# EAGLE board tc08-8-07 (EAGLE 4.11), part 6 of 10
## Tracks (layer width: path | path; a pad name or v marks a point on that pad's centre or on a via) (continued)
IM_05\  (via drill 0.61) (continued)
  Bottom 0.254: B04.S1 326.11,161.59 327.06,160.64 334.05,160.64 335,161.59 337.54,161.59 B03.S1 | v285.79,37.45 287.69,37.45 292.77,42.53 307.06,42.53 307.38,42.21 308.65,42.21 309.28,42.85 313.09,42.85 313.73,42.21 316.58,42.21 317.54,43.17 320.71,43.17 321.66,44.12 D04.L1 | v282.61,15.54 281.98,14.91 265.47,14.91 265.15,14.59 260.39,14.59 v260.07,14.91 | v256.26,11.1 255.94,11.42 238.48,11.42 238.16,11.1 v235.94,11.1 | v234.67,21.58 234.03,20.94 218.48,20.94 213.4,15.86 181.65,15.86 181.01,16.5 178.79,16.5 178.15,15.86 110.53,15.86 109.26,17.13 v96.24,17.13 | v94.65,83.17 98.14,86.66 v99.1,86.66 | v106.72,210.17 v109.57,213.03 | v109.57,222.24 110.84,223.51 134.02,223.51 134.66,224.14 138.15,224.14 141.01,227 v151.48,227 | v158.15,269.55 159.74,271.13 166.09,271.13 166.41,271.45 187.36,271.45 v188,270.81 | v190.54,272.72 190.85,272.4 194.03,272.4 194.66,271.77 205.46,271.77 205.78,272.09 207.05,272.09 207.36,271.77 214.98,271.77 217.21,273.99 219.75,273.99 220.38,274.62 v221.02,274.62 | v241.02,287.96 241.34,288.28 266.74,288.28 268.96,286.05 303.25,286.05 303.88,286.69 320.71,286.69 v321.03,287.01 321.35,286.69 363.26,286.69 v365.16,284.79 | v349.92,176.52 v347.06,173.66 | v350.24,179.37 349.6,180.01 349.6,191.12 352.46,191.12 v353.73,192.39 | v356.91,195.57 356.91,198.43 355.64,199.7 v355.64,200.96 | v364.21,223.19 367.07,226.05 369.92,226.05 370.56,226.68 370.56,230.18 v368.97,230.18 | v368.97,241.29 368.97,249.54 v365.48,249.54
IM_06\  (via drill 0.61)
  Top 0.254: v368.34,43.17 369.61,44.44 369.61,72.69 370.88,73.97 370.88,94.92 370.24,95.55 370.24,97.46 371.83,99.05 371.83,114.29 371.51,114.61 371.51,147.94 373.42,149.85 373.42,239.06 v372.78,239.7 | v339.13,196.2 339.44,196.52 339.44,209.86 338.81,210.49 338.81,224.14 339.44,224.78 339.44,233.03 339.13,233.35 339.13,237.16 340.08,238.11 v340.08,239.7
  Bottom 0.254: 327.38,188.58 327.7,188.58 328.97,187.31 B03.H2 | 327.38,188.58 320.71,188.58 319.76,187.63 B04.H2 | v368.34,43.17 364.53,39.36 349.92,39.36 349.6,39.68 327.38,39.68 326.11,40.95 D04.M1 | v372.78,239.7 v340.08,239.7 336.59,243.19 327.06,243.19 326.11,244.14 A04.M1 | 327.38,188.58 327.38,192.08 337.54,192.08 337.86,192.39 338.81,192.39 339.44,193.03 339.44,196.2 v339.13,196.2
IM_07\
  Top 0.254: D04.P1 325.79,35.55 326.43,36.18 326.43,40.31 327.06,40.95 327.06,48.57 327.38,48.88 327.38,50.15 326.74,50.79 326.74,55.23 326.43,55.55 326.43,59.36 327.06,60 327.06,100.32 326.74,100.63 326.74,119.69 327.06,120 327.06,132.07 326.74,132.39 326.74,146.67 327.38,147.31 327.38,182.55 328.33,183.5 B03.J2 328.33,184.77 328.33,187.31 326.74,188.9 326.74,204.14 327.06,204.46 327.06,215.25 326.74,215.57 326.74,232.4 326.43,232.71 326.43,236.84 325.79,237.48 A04.P1
  Bottom 0.254: B04.J2 316.58,184.46 317.54,185.41 325.16,185.41 326.11,184.46 328.01,184.46 B03.J2
IM_08\  (via drill 0.61)
  Top 0.254: v368.65,33.64 370.24,35.23 370.24,72.38 371.51,73.65 371.51,95.24 370.88,95.87 370.88,97.14 372.46,98.73 v372.46,114.92 | v356.59,146.67 356.27,146.99 356.27,154.61 355.32,155.56 v355.32,163.18 355.32,169.21 355.95,169.85 355.95,177.47 359.13,180.64 359.13,194.93 358.81,195.25 358.81,197.15 359.45,197.79 359.45,200.65 358.81,201.28 358.81,203.51 360.08,204.77 360.08,206.05 361.99,207.95 361.99,218.11 361.67,218.43 361.67,226.36 361.99,226.68 361.99,228.9 361.67,229.22 v361.67,233.03 | v344.84,166.36 v344.84,163.5
  Bottom 0.254: v368.65,33.64 347.7,33.64 344.84,30.78 343.89,30.78 343.25,30.15 337.86,30.15 337.22,29.51 333.41,29.51 333.09,29.83 331.19,29.83 330.87,29.51 326.74,29.51 326.11,28.88 D04.S1 | v372.46,114.92 369.61,117.78 369.61,146.67 364.53,146.67 364.21,146.36 356.91,146.36 v356.59,146.67 | v355.32,163.18 345.16,163.18 v344.84,163.5 | v344.84,166.36 344.21,166.99 343.25,166.99 335.63,174.61 333.73,174.61 332.46,175.88 331.19,175.88 328.97,173.66 328.97,172.07 B03.N2 328.01,171.76 325.79,171.76 324.84,172.71 317.54,172.71 316.58,171.76 B04.N2 | v361.67,233.03 350.24,233.03 349.92,232.71 346.11,232.71 345.79,233.03 343.89,233.03 343.57,232.71 339.76,232.71 339.44,233.03 337.54,233.03 337.22,232.71 334.36,232.71 334.05,233.03 331.19,233.03 330.87,232.71 326.74,232.71 326.11,232.08 A04.S1
IM_09\  (via drill 0.61)
  Top 0.254: 314.68,167.95 314.68,151.75 315.31,151.12 315.31,140.96 314.68,140.32 314.68,88.25 315.95,86.98 315.95,73.33 314.68,72.06 314.68,69.2 315,68.88 315,64.76 315.63,64.12 D04.D2 | 314.68,167.95 v316.58,169.85 | 314.68,167.95 314.68,203.82 315.95,205.09 315.95,219.7 314.68,220.97 314.68,230.49 314.36,230.81 314.36,264.78 315.63,266.05 A04.D2
  Bottom 0.254: v316.58,169.85 316.9,169.53 330.24,169.53 331.19,168.58 B03.P2
IM_10\  (via drill 0.61)
  Top 0.254: v319.44,51.74 317.85,53.33 317.85,54.6 318.17,54.92 318.17,59.04 318.81,59.68 D04.E2 | v321.66,52.38 321.35,52.06 321.35,51.74 321.03,51.42 321.03,48.57 v321.35,48.25 | v314.04,45.71 313.73,45.39 313.73,42.21 314.36,41.58 314.36,39.36 313.73,38.72 313.73,35.86 314.36,35.23 314.36,33.96 v314.04,33.64 | v303.57,28.25 301.98,26.66 301.98,22.85 v302.3,22.53 | v288.01,20.31 287.69,19.99 287.69,9.19 283.25,4.75 276.9,4.75 276.9,18.09 276.58,18.4 276.58,20.94 v276.9,21.26 | v193.08,77.77 192.12,78.73 192.12,83.81 v192.44,84.13
  Route2 0.254: v270.55,21.89 255.62,36.82 254.35,36.82 252.77,35.23 252.13,35.23 v249.59,37.77 | v192.44,84.13 202.92,94.6 202.92,98.41 204.19,99.68 205.14,99.68 206.09,100.63 206.09,101.59 207.36,102.86 208,102.86 209.59,104.44 209.59,106.67 210.54,107.62 210.54,108.57 212.44,110.48 212.44,122.86 225.14,135.56 225.14,140.96 245.46,161.28 245.46,161.91 v244.51,162.86 | v252.77,160.96 253.72,161.91 253.72,162.86 261.66,170.8 261.66,172.39 263.24,173.98 263.24,177.79 v266.74,181.28 | v264.2,194.61 262.61,196.2 269.91,203.51 269.91,207.31 263.88,213.35 269.28,218.74 270.23,218.74 270.55,219.06 272.77,219.06 277.21,223.51 278.17,223.51 278.8,224.14 278.8,226.36 284.2,231.76 285.47,231.76 290.23,236.52 313.73,236.52 318.81,241.61 320.71,241.61 331.19,252.08 331.82,252.08 333.73,253.99 333.73,257.16 336.59,260.02 336.59,260.66 327.38,269.86 322.93,265.42 321.35,265.42 319.76,263.83 A04.E2
  Route15 0.254: v242.92,37.77 234.99,45.71 234.99,46.66 234.03,47.61 232.76,47.61 223.87,56.5 223.24,56.5 221.33,58.41 217.52,58.41 216.25,59.68 216.25,60.63 215.3,61.58 214.35,61.58 v199.11,76.82 | v244.51,162.86 245.46,162.86 246.42,163.82 248,163.82 248.96,164.77 v252.77,160.96 | v266.74,181.28 268.64,183.18 267.69,184.14 267.69,186.04 267.05,186.68 267.05,187.95 v268.01,188.9
  Bottom 0.254: v319.44,51.74 319.76,52.06 321.35,52.06 v321.66,52.38 | v321.35,48.25 321.35,46.34 314.68,46.34 v314.04,45.71 | v314.04,33.64 313.73,33.32 308.65,33.32 v303.57,28.25 | v302.3,22.53 300.07,20.31 v288.01,20.31 | v276.9,21.26 276.58,20.94 271.82,20.94 270.86,21.89 v270.55,21.89 | v249.59,37.77 249.27,37.45 247.37,37.45 246.73,36.82 243.88,36.82 v242.92,37.77 | v199.11,76.82 198.16,77.77 v193.08,77.77 | v268.01,188.9 268.64,189.54 269.59,189.54 270.23,190.17 270.23,192.39 267.05,192.39 264.83,194.61 v264.2,194.61
IM_11\  (via drill 0.61)
  Top 0.254: v319.12,58.09 318.81,57.77 318.81,54.6 D04.H2 | v352.46,83.49 352.78,83.81 352.78,90.79 v353.1,91.11 | v360.72,130.16 361.67,131.11 361.67,133.97 360.4,135.24 v360.4,137.46 | v321.35,256.53 321.03,256.21 321.03,251.77 v321.35,251.45 | v318.81,249.23 317.54,247.96 317.54,233.35 315.63,231.45 v315.63,230.81 | v312.46,229.54 311.82,228.9 311.82,226.36 311.5,226.05 311.5,222.87 312.77,221.6 v312.77,219.38 | v318.17,211.12 321.35,207.95 321.35,204.14 v320.71,203.51 | v325.79,190.8 326.11,190.49 326.11,188.58 327.38,187.31 v327.38,185.73 | v335,180.01 333.73,178.74 333.73,167.63 v334.68,166.68
  Route2 0.254: v360.72,124.13 357.86,126.99 360.72,129.84 v360.72,130.16 | v315.63,230.81 314.04,229.22 312.77,229.22 v312.46,229.54
  Route15 0.254: v323.25,60.31 338.49,75.55 338.17,75.87 338.17,76.82 342.62,81.27 342.94,80.95 344.52,80.95 v346.11,79.36 | v357.54,108.25 360.4,111.11 v357.22,114.29 | v356.59,140.01 356.59,141.59 355.64,142.55 355.64,147.94 348.65,154.93 348.65,155.88 345.48,159.05 342.94,159.05 341.98,160.01 336.59,160.01 332.14,164.45 | 332.14,164.45 v329.28,167.31 | v320.71,203.51 320.71,202.87 321.98,201.6 321.98,200.33 324.2,198.11 324.2,196.84 326.74,194.3 326.74,191.76 v325.79,190.8 | v331.82,185.73 330.55,184.46 v335,180.01 | v334.68,166.68 332.46,164.45 332.14,164.45
  Bottom 0.254: v319.12,58.09 320.08,59.04 320.08,59.36 321.03,60.31 v323.25,60.31 | v346.11,79.36 349.29,82.54 351.51,82.54 v352.46,83.49 | v353.1,91.11 354.68,92.7 355.95,92.7 356.91,93.65 360.72,93.65 366.11,99.05 367.07,99.05 368.65,100.63 368.65,107.3 361.67,107.3 361.03,106.67 359.13,106.67 v357.54,108.25 | v357.22,114.29 357.22,115.24 355.95,116.51 355.95,119.37 361.35,119.37 363.26,121.27 366.75,121.27 367.07,120.96 367.7,120.96 368.34,121.59 368.34,122.86 364.53,122.86 364.21,122.54 362.3,122.54 v360.72,124.13 | v360.4,137.46 357.86,140.01 v356.59,140.01 | v329.28,167.31 328.97,166.99 324.52,166.99 322.93,168.58 319.76,168.58 B04.P2 | v321.35,256.53 320.08,256.53 319.76,256.85 A04.H2 | v321.35,251.45 321.35,249.23 v318.81,249.23 | v312.77,219.38 317.54,214.62 317.54,211.12 v318.17,211.12 | v327.38,185.73 328.33,186.68 330.55,186.68 331.51,185.73 v331.82,185.73
INT_RQ\  (via drill 0.61)
  Top 0.254: v282.93,233.35 282.29,232.71 282.29,223.83 281.66,223.19 281.66,216.84 v282.61,215.89
  Route15 0.254: v246.42,236.52 242.92,240.02 239.11,240.02 230.22,248.91 229.27,248.91 228.95,249.23 227.37,249.23 226.1,250.49 224.51,250.49 A12.K1 | v299.12,214.93 299.12,212.08 304.84,206.36 304.84,206.05 306.11,204.77 307.69,204.77 308.96,203.51 B05.B1
  Bottom 0.254: v246.42,236.52 246.73,236.21 268.01,236.21 270.55,233.67 280.71,233.67 281.34,234.3 281.98,234.3 v282.93,233.35 | v282.61,215.89 283.25,215.25 298.8,215.25 v299.12,214.93
IOP_1  (via drill 0.61)
  Top 0.254: v356.27,49.52 355.95,49.83 355.95,69.2 v356.27,69.52 | v335.63,71.43 335.63,87.62 336.27,88.25 336.27,91.43 v334.36,93.33 | v311.5,93.97 311.82,94.28 311.82,97.46 311.5,97.78 311.5,100 312.14,100.63 312.14,103.18 v311.19,104.13 | v344.52,248.59 A02.K2
  Route2 0.254: v363.89,233.99 371.19,226.68 371.19,225.73 368.65,223.19 368.65,220.97 368.34,220.65 368.34,214.62 372.78,210.17 372.78,150.17 371.19,148.58 371.19,147.62 370.88,147.31 370.88,106.35 372.78,104.44 372.78,98.1 371.51,96.83 371.51,72.38 370.88,71.74 370.88,71.11 v371.83,70.16
  Route15 0.254: v344.52,248.59 344.84,248.59 354.37,239.06 v354.37,238.75 | v371.83,60.95 371.83,56.18 371.19,55.55 v372.46,54.28
  Bottom 0.254: 311.19,104.44 307.06,104.44 C05.P2 | 311.19,104.44 312.14,103.49 317.54,103.49 318.49,104.44 C04.P2 | v356.27,69.52 354.37,71.43 v335.63,71.43 | v334.36,93.33 330.24,93.33 329.6,92.7 326.74,92.7 325.79,93.65 317.85,93.65 316.9,92.7 315,92.7 313.73,93.97 v311.5,93.97 | v311.19,104.13 311.19,104.44 | D02.K2 345.16,47.93 345.79,48.57 349.92,48.57 350.87,49.52 v356.27,49.52 367.7,49.52 v372.46,54.28 | v354.37,238.75 356.27,236.84 357.86,236.84 359.45,238.43 360.72,238.43 363.89,235.26 v363.89,233.99 | v371.83,70.16 v371.83,60.95
IOP_2  (via drill 0.61)
  Top 0.254: v358.81,40.95 358.49,41.26 v358.49,67.93 | v329.28,71.74 328.97,72.06 v328.97,87.3 | v308.01,88.57 308.33,88.89 308.33,89.52 308.96,90.16 308.96,92.7 v308.33,93.33 | v303.57,98.1 303.57,100.95 C05.R2 | v331.82,247.32 331.51,247 331.51,246.68 330.55,245.73 330.55,243.19 v331.51,242.24 | v287.69,171.76 286.1,170.17 v286.1,150.8
  Route2 0.254: v331.51,242.24 316.58,227.32 316.27,227.32 315.63,226.68 315.63,223.83 314.68,222.87 314.68,220.33 314.04,219.7 314.04,210.17 306.11,202.24 305.15,202.24 v286.74,183.82
  Route15 0.254: v303.57,98.1 v308.33,93.33 | v286.74,183.82 286.74,183.5 288.64,181.6 288.64,172.71 v287.69,171.76 | v286.1,150.8 286.1,141.59 288.64,139.05 288.64,138.1 289.28,137.46 289.28,132.39 299.12,122.54 299.12,121.27 299.44,120.96 299.44,120 301.34,118.1 301.34,111.75 304.52,108.57 304.52,103.18 303.57,102.22 C05.R2
  Bottom 0.254: C05.R2 303.88,101.91 308.01,101.91 308.96,102.86 310.23,102.86 311.19,101.91 315.31,101.91 C04.R2 | v358.81,40.95 357.86,39.99 350.24,39.99 349.92,40.31 345.79,40.31 345.16,40.95 D02.M2 | v358.49,67.93 357.86,68.57 334.05,68.57 330.87,71.74 v329.28,71.74 | v328.97,87.3 328.65,86.98 309.6,86.98 v308.01,88.57 | v331.82,247.32 332.14,247.32 333.09,246.37 338.17,246.37 339.13,245.42 343.25,245.42 343.89,244.78 A02.M2
IOP_4  (via drill 0.61)
  Top 0.254: 342.62,96.83 342.62,92.06 344.52,90.16 344.52,74.92 342.94,73.33 342.94,40.95 343.57,40.31 343.57,36.18 344.21,35.55 D02.P2 | 342.62,96.83 v341.03,98.41 | 342.62,96.83 342.62,133.97 342.3,134.29 342.3,137.15 342.62,137.46 342.62,140.32 342.3,140.64 342.3,143.5 342.94,144.13 342.94,180.64 342.62,180.96 342.62,197.47 342.3,197.79 342.3,200.65 342.62,200.96 342.62,206.36 344.52,208.27 344.52,222.24 342.94,223.83 342.94,232.08 343.57,232.71 343.57,236.84 344.21,237.48 A02.P2
  Bottom 0.254: 317.54,99.68 312.14,99.68 311.19,98.73 307.06,98.73 C05.S2 | 317.54,99.68 318.49,98.73 C04.S2 | v341.03,98.41 339.76,99.68 317.54,99.68
LDMF  (via drill 0.61)
  Top 0.254: v228.64,55.55 228.32,55.87 228.32,59.36 227.05,60.63 D11.D2 227.37,64.12 227.37,67.93 v227.68,68.25 | v291.18,110.48 290.23,111.43 v290.23,112.38 | v256.26,96.51 255.62,95.87 v255.62,93.97 | v243.24,89.52 242.92,89.21 v242.92,79.36
  Route2 0.254: v294.04,113.33 306.74,126.03 306.74,126.99 309.6,129.84 312.14,129.84 C05.E1 | v284.52,112.7 279.75,112.7 274.36,107.3 273.72,107.3 v268.64,102.22 | v243.24,89.52 v245.78,92.06 | v236.26,78.09 236.26,74.6 235.3,73.65 235.3,72.06 233.72,70.47 D11.B1
  Bottom 0.254: v228.64,55.55 230.54,55.55 231.49,54.6 235.62,54.6 235.94,54.28 D11.H1 | v227.68,68.25 231.49,68.25 232.76,69.52 D11.B1 | v291.18,110.48 v294.04,113.33 | v290.23,112.38 289.91,112.7 v284.52,112.7 | v268.64,102.22 267.69,101.27 266.74,101.27 265.78,100.32 265.15,100.32 263.24,98.41 263.24,97.14 260.7,97.14 260.07,97.78 257.53,97.78 v256.26,96.51 | v255.62,93.97 254.35,92.7 250.54,92.7 249.91,93.33 247.05,93.33 v245.78,92.06 | v242.92,79.36 241.65,78.09 v236.26,78.09
LDMF\  (via drill 0.61)
  Top 0.254: v309.28,137.15 309.28,136.51 308.33,135.56 308.33,128.58 309.28,127.62 C05.F1 | v318.49,139.05 319.44,140.01 v319.44,140.96 | v321.98,143.18 321.98,148.58 v319.44,151.12 | v285.15,161.59 285.47,161.91 285.47,165.72 v284.52,166.68
  Route15 0.254: v294.04,152.71 v285.15,161.59
  Bottom 0.254: v309.28,137.15 309.92,137.78 317.22,137.78 v318.49,139.05 | v319.44,140.96 321.66,143.18 v321.98,143.18 | v319.44,151.12 319.12,150.8 309.28,150.8 308.65,151.43 304.2,151.43 303.88,151.12 295.63,151.12 v294.04,152.71 | v284.52,166.68 284.2,166.99 269.91,166.99 268.96,167.95 B08.P2
LPB_00  (via drill 0.61)
  Top 0.254: v46.71,218.11 46.71,221.6 48.3,223.19 48.3,227.32 48.93,227.95 A25.T2 | v44.8,216.21 44.17,215.57 44.17,47.29 50.52,40.95 50.52,39.04 v80.36,9.19 | v269.59,7.93 269.59,44.44 266.74,47.29 v266.74,56.5 | v269.91,126.35 269.91,127.3 270.86,128.26 270.86,132.39 271.18,132.7 C08.D1 | v290.87,92.38 291.82,91.43 291.82,83.17 291.18,82.54 291.18,74.28 v291.5,73.97 | v278.8,67.93 277.85,66.98 v277.85,65.39
  Route15 0.254: v274.67,121.59 v269.91,126.35 | v268.64,115.24 284.83,99.05 284.83,98.41 v290.87,92.38
  Bottom 0.254: v44.8,216.21 v46.71,218.11 | v80.36,9.19 81.95,7.61 222.29,7.61 222.92,8.24 230.86,8.24 232.76,6.34 259.12,6.34 260.39,7.61 269.28,7.61 v269.59,7.93 | v266.74,56.5 270.23,60 272.45,60 | 272.45,60 274.04,60 D08.E1 | v274.67,121.59 275.94,121.59 276.58,120.96 276.58,118.73 272.13,118.73 v268.64,115.24 | v291.5,73.97 288.64,71.11 282.61,71.11 279.44,67.93 v278.8,67.93 | 272.45,60 v277.85,65.39
LPB_00\  (via drill 0.61)
  Top 0.254: v260.07,39.99 260.7,40.63 260.7,51.1 v261.66,52.06
  Bottom 0.254: v260.07,39.99 250.86,39.99 249.91,40.95 D10.M1 | v261.66,52.06 262.29,52.69 264.2,52.69 268.32,56.82 270.86,56.82 D08.F1
LPB_01  (via drill 0.61)
  Top 0.254: v13.05,78.09 19.09,72.06 v19.09,44.75 | v275.31,7.61 275.94,8.24 275.94,36.5 271.82,40.63 271.82,43.8 D08.L1 | v296.26,92.38 298.17,90.47 298.17,85.08 297.22,84.13 v297.22,71.43 | v291.18,65.39 v291.18,67.93
  Route15 0.254: v271.5,110.8 268.32,107.62 271.82,104.13 v271.82,103.81 | v287.37,101.59 287.37,101.27 v296.26,92.38
  Bottom 0.254: v13.05,78.09 5.43,78.09 5.43,219.7 12.42,226.68 37.5,226.68 37.82,227 40.04,227 40.36,226.68 42.26,226.68 44.8,224.14 46.71,224.14 47.03,224.46 51.15,224.46 51.79,225.09 A25.U2 | v19.09,44.75 56.87,6.97 222.6,6.97 223.24,7.61 230.54,7.61 232.45,5.7 259.43,5.7 260.7,6.97 274.67,6.97 v275.31,7.61 | v271.5,110.8 272.45,110.8 273.72,112.07 273.72,112.7 273.09,113.33 272.45,113.33 272.13,113.02 270.23,113.02 270.23,115.88 271.18,116.83 273.72,116.83 274.04,117.14 C08.K1 | v271.82,103.81 272.13,103.49 275.94,103.49 276.58,104.13 279.75,104.13 281.02,102.86 286.1,102.86 v287.37,101.59 | v297.22,71.43 296.9,71.11 294.68,71.11 291.5,67.93 v291.18,67.93 | v291.18,65.39 291.18,64.76 291.82,64.12 291.82,60 290.55,60 288.33,57.77 288.33,54.92 288.64,54.6 288.64,48.88 285.47,48.88 282.93,46.34 274.04,46.34 272.45,44.75 272.13,44.75 D08.L1
LPB_01\  (via drill 0.61)
  Top 0.254: v261.97,38.72 262.29,38.4 v262.29,36.82
  Bottom 0.254: v261.97,38.72 260.07,38.72 259.43,39.36 247.69,39.36 246.73,38.4 D10.N1 | v262.29,36.82 268.32,36.82 272.45,40.95 274.04,40.95 D08.M1
LPB_02  (via drill 0.61)
  Top 0.254: v55.92,218.11 55.92,219.06 52.74,219.06 49.88,221.92 A25.V2 | v45.12,209.22 44.8,208.9 44.8,90.16 47.03,87.94 47.03,73.97 51.15,69.84 51.15,40.63 v77.19,14.59 | v273.4,9.51 v273.4,26.02 | v294.04,90.16 294.36,89.84 294.36,74.28 294.99,73.65 294.99,71.11 294.36,70.47 v294.36,69.52 | v296.26,65.08 v296.26,67.61 | v273.72,37.14 273.4,36.82 273.4,30.15 274.36,29.2 D08.S1
  Route15 0.254: v273.72,101.59 273.72,101.27 v283.88,91.11
  Bottom 0.254: v55.92,218.11 55.92,217.48 57.19,216.21 57.19,210.17 54.65,210.17 53.38,208.9 45.44,208.9 v45.12,209.22 | v77.19,14.59 82.9,8.88 221.65,8.88 222.29,9.51 231.49,9.51 233.4,7.61 258.48,7.61 260.39,9.51 v273.4,9.51 | v273.4,26.02 273.4,28.25 274.04,28.25 D08.S1 | v283.88,91.11 284.83,90.16 v294.04,90.16 | v296.26,67.61 v294.36,69.52 | v296.26,65.08 292.45,61.27 292.45,59.36 290.87,59.36 288.96,57.46 288.96,55.23 292.14,52.06 292.14,50.15 291.82,50.15 284.83,43.17 279.75,43.17 v273.72,37.14 | v273.72,101.59 C08.R1
LPB_02\  (via drill 0.61)
  Top 0.254: v271.18,33.64 272.77,33.64 272.77,27.93 274.36,26.34 274.36,22.85 D08.U1
  Bottom 0.254: v271.18,33.64 250.86,33.64 249.91,34.6 D10.P1
LPB_03  (via drill 0.61)
  Top 0.254: D08.H2 268.01,54.6 267.69,54.92 267.69,58.09 266.42,59.36 266.42,64.76 266.1,65.08 266.1,68.88 266.74,69.52 266.74,118.1 268.32,119.69 C08.H2 | v30.52,274.62 28.29,274.62 28.29,247.64 25.75,245.1 25.75,243.83 27.34,242.24 v27.34,240.65 | v40.68,223.83 40.04,223.19 v40.04,219.7 | v47.98,211.44 48.61,210.81 48.61,207 51.47,204.14 51.47,200.96 51.15,200.65 51.15,148.26 54.33,145.08 54.33,107.3 v55.92,105.72 | v115.61,95.24 116.56,94.28 116.56,93.33 120.69,89.21 120.69,86.98 v122.59,85.08 | v151.17,74.92 158.47,74.92 158.47,57.77 161.64,54.6 161.64,29.83 v162.6,28.88 | v175.3,27.61 178.47,27.61 v180.06,26.02
  Route2 0.254: v146.4,79.68 v151.17,74.92 | v213.4,28.56 217.21,24.75 220.06,27.61 221.02,27.61 223.24,29.83 229.59,29.83 239.11,39.36 244.19,39.36 245.46,40.63 246.73,40.63 251.81,45.71 254.67,45.71 255.31,46.34 256.58,46.34 258.8,48.57 261.02,48.57 264.51,52.06 266.1,52.06 267.69,53.64 D08.H2
  Route15 0.254: v27.34,240.65 34.33,233.67 34.33,232.71 41.31,225.73 41.31,224.46 v40.68,223.83 | v180.06,26.02 182.28,23.8 185.46,23.8 191.49,29.83 194.03,29.83 v194.35,29.51
  Bottom 0.254: v30.52,274.62 37.82,274.62 39.09,275.9 A26.A2 | v40.04,219.7 46.71,213.03 47.03,213.03 47.98,212.08 v47.98,211.44 | v55.92,105.72 64.49,97.14 113.7,97.14 v115.61,95.24 | v122.59,85.08 127.99,79.68 v146.4,79.68 | v162.6,28.88 163.55,27.93 165.45,27.93 166.09,27.29 167.36,27.29 167.68,27.61 172.12,27.61 172.44,27.29 174.98,27.29 v175.3,27.61 | v194.35,29.51 194.66,29.83 211.81,29.83 213.08,28.56 v213.4,28.56
LPB_03\  (via drill 0.61)
  Top 0.254: v267.37,32.06 267.05,32.37 267.05,46.03 265.47,47.61 265.47,50.15 D08.J2
  Bottom 0.254: v267.37,32.06 265.78,30.47 251.81,30.47 251.18,31.1 247.05,31.1 246.73,31.42 D10.R1
LPB_04  (via drill 0.61)
  Top 0.254: v303.57,65.39 304.2,66.03 304.2,68.88 304.52,69.2 304.52,71.43 303.57,72.38 v303.57,76.5 | v268.32,85.08 270.23,86.98 270.23,89.52 271.5,90.79 271.5,92.7 v272.45,93.65 | v13.05,271.13 12.42,270.5 12.42,247 9.88,244.46 9.88,55.23 v10.83,54.28 | v264.2,8.56 263.88,8.88 263.88,33.01 v265.47,34.6
  Route15 0.254: v272.45,93.65 274.04,95.24 266.74,102.54 266.74,106.03 265.47,107.3 C08.N2
  Bottom 0.254: v303.57,65.39 303.25,65.08 298.8,65.08 298.8,55.87 285.47,42.53 280.39,42.53 273.4,35.55 269.28,35.55 268.96,35.23 D08.P2 267.69,34.6 v265.47,34.6 | v303.57,76.5 303.25,76.19 282.93,76.19 281.98,77.14 281.02,77.14 279.75,75.87 269.91,75.87 266.74,79.05 266.74,85.08 v268.32,85.08 | v13.05,271.13 34.33,271.13 35.91,272.72 A26.B2 | v10.83,54.28 54.96,10.15 80.68,10.15 82.59,8.24 221.97,8.24 222.6,8.88 231.18,8.88 233.08,6.97 258.8,6.97 260.39,8.56 v264.2,8.56
LPB_04\
  Bottom 0.254: D10.R2 240.38,32.06 241.34,33.01 263.56,33.01 264.51,32.06 D08.R2
LPB_05  (via drill 0.61)
  Top 0.254: v270.55,20.62 270.23,20.31 270.23,8.56 274.36,4.43 274.36,1.57 274.67,1.26 309.28,1.26 309.28,13.96 v312.77,17.45 | v291.5,23.8 291.82,24.12 291.82,31.1 292.14,31.42 v292.14,33.96 | v281.66,38.72 279.75,40.63 279.75,51.1 280.39,51.74 280.39,52.38 v279.44,53.33 | v272.13,54.6 273.4,54.6 274.04,55.23 274.04,59.04 273.4,59.68 273.4,63.49 v273.72,63.81 | v267.69,68.57 v267.69,71.11 | v265.15,71.74 264.83,72.06 v264.83,85.08 | v267.69,88.25 268.01,88.57 268.01,91.43 C08.U2 | v26.71,202.24 v26.71,204.77 | v46.07,183.18 47.34,181.92 v47.34,144.45 | v61,130.8 60.68,130.48 60.68,43.8 v89.89,14.59 | v102.59,11.42 105.13,8.88 149.26,8.88 v149.26,18.72 | v154.02,19.04 156.56,16.5 179.74,16.5 v179.74,19.35 | v184.19,18.09 187.68,18.09 187.68,20.31 v189.27,21.89 | v241.34,18.09 v246.42,13.01 | v39.72,266.37 A26.C2
  Route2 0.254: v264.83,85.08 264.83,85.39 v267.69,88.25 | v149.26,18.72 151.48,16.5 v154.02,19.04 | v179.74,19.35 182.6,16.5 v184.19,18.09 | v205.14,18.72 207.36,16.5 209.27,18.4 209.9,18.4 213.71,22.21 215.62,22.21 216.89,23.48 218.16,23.48 225.14,16.5 234.03,16.5 v235.62,18.09
  Route15 0.254: v273.72,63.81 273.72,64.44 v271.82,66.35 | v10.83,214.93 v1.94,223.83 | v193.08,18.09 v189.27,21.89 | v246.42,13.01 248,13.01 252.77,17.77 254.04,17.77 254.67,17.13 262.93,17.13 264.51,18.72 D08.V2
  Bottom 0.254: v270.55,20.62 268.96,20.62 267.69,19.35 265.78,19.35 D08.V2 | v312.77,17.45 312.77,20.62 305.47,20.62 302.3,23.8 v291.5,23.8 | v292.14,33.96 289.6,36.5 283.88,36.5 v281.66,38.72 | v279.44,53.33 278.8,52.69 274.04,52.69 v272.13,54.6 | v271.82,66.35 269.59,68.57 v267.69,68.57 | v267.69,71.11 267.05,71.74 v265.15,71.74 | v39.72,266.37 38.14,264.78 7.97,264.78 1.62,258.43 1.62,232.71 2.26,232.71 2.89,232.08 2.89,223.83 v1.94,223.83 | v10.83,214.93 10.83,207.63 16.55,207.63 19.09,205.09 21.31,205.09 23.53,207.31 24.17,207.31 v26.71,204.77 | v26.71,202.24 35.28,193.66 35.28,180.64 37.82,180.64 38.45,181.28 38.45,182.87 45.76,182.87 v46.07,183.18 | v61,130.8 v47.34,144.45 | v89.89,14.59 93.06,11.42 v102.59,11.42 | v193.08,18.09 193.39,17.77 204.19,17.77 v205.14,18.72 | v235.62,18.09 235.94,17.77 241.02,17.77 v241.34,18.09
LPB_05\
  Top 0.254: D10.U2 242.29,22.53 240.07,24.75 D10.T2 240.38,25.71 242.61,27.93 D10.S2
  Bottom 0.254: D08.V1 268.32,19.04 266.42,17.13 250.86,17.13 246.1,21.89 243.56,21.89 D10.U2
LPB_NOT_EQ_1  (via drill 0.61)
  Top 0.254: v34.33,51.1 34.64,51.42 34.64,143.5 33.69,144.45 v33.69,151.43 | v89.57,171.76 89.25,172.07 89.25,182.23 v90.84,183.82 | v118.78,188.58 119.42,189.22 119.73,189.22 120.37,189.85 120.37,195.89 v122.59,198.11 | v125.13,200.33 127.35,202.55 127.35,212.08 128.94,213.67 v128.94,217.48 | v150.21,218.11 149.9,218.43 149.9,221.29 149.58,221.6 149.58,231.13 v150.85,232.4 | v159.74,233.35 161.01,234.62 161.01,236.52 161.64,237.16 v163.87,237.16
  Route2 0.254: v206.09,223.83 208.95,223.83 209.27,224.14 212.13,224.14 222.29,234.3 223.24,234.3 v236.57,247.64
  Route15 0.254: v196.25,28.56 204.51,20.31 208.63,20.31 210.22,18.72 211.81,18.72 214.03,16.5 215.62,18.09 217.84,18.09 221.02,14.91 223.87,14.91 226.1,12.69 232.13,12.69 238.16,18.72 239.11,18.72 D10.V2 | v170.22,237.16 171.8,237.16 v182.28,226.68 | v241.34,247 244.83,247 245.46,246.37 247.05,246.37 248.64,244.78 A10.M1
  Bottom 0.254: v196.25,28.56 194.03,28.56 192.76,29.83 93.06,29.83 92.75,29.51 91.48,29.51 90.52,30.47 54.96,30.47 v34.33,51.1 | v33.69,151.43 45.44,163.18 61.95,163.18 64.49,160.64 78.46,160.64 v89.57,171.76 | v90.84,183.82 93.06,186.04 111.8,186.04 114.34,188.58 v118.78,188.58 | v122.59,198.11 124.81,200.33 v125.13,200.33 | v128.94,217.48 129.26,217.16 147.04,217.16 147.99,218.11 v150.21,218.11 | v150.85,232.4 151.48,233.03 159.42,233.03 v159.74,233.35 | v163.87,237.16 165.77,237.16 166.09,236.84 169.9,236.84 v170.22,237.16 | v182.28,226.68 184.82,224.14 205.78,224.14 v206.09,223.83 | v236.57,247.64 236.89,247.32 238.16,247.32 239.11,246.37 240.7,246.37 v241.34,247
LPB_TO_DTB  (via drill 0.61)
  Top 0.254: C08.M2 268.64,111.75 269.59,112.7 269.59,116.83 271.18,118.41 271.18,120 C08.J1 | v265.47,122.22 265.47,126.35 C08.F2 | 275.94,120.64 275.94,106.35 274.99,105.4 C08.P1 | 275.94,120.64 275.94,134.93 274.99,135.88 C08.C1 274.99,137.15 275.94,138.1 v275.94,209.54 | v228,209.54 227.68,209.86 227.68,216.21 228.32,216.84 228.32,222.87 227.37,223.83 227.37,227.95 A11.T2 | 275.94,120.64 v275.63,120.64
  Bottom 0.254: v265.47,122.22 266.74,120.96 270.86,120.96 C08.J1 v275.63,120.64 | C08.T2 265.47,95.87 265.47,99.68 266.42,99.68 267.37,100.63 268.32,100.63 270.86,103.18 270.86,104.76 C08.P1 | v228,209.54 228.32,209.22 275.63,209.22 v275.94,209.54
M-STOP\  (via drill 0.61)
  Top 0.254: D14.L1 194.98,45.07 194.03,46.03 194.03,72.06 194.66,72.69 194.66,87.62 194.03,88.25 194.03,93.65 193.08,94.6 193.08,97.46 193.71,98.1 193.71,132.07 193.39,132.39 193.39,135.88 193.71,136.2 193.71,170.17 193.39,170.49 193.39,188.58 194.03,189.22 194.03,191.44 194.98,192.39 194.98,196.2 B14.D1 | v271.5,115.88 270.23,115.88 270.23,111.75 269.59,111.11 269.59,96.19 268.01,94.6 v268.01,93.97 | v264.51,92.38 263.88,91.74 263.88,76.82 264.2,76.5 264.2,70.79 263.88,70.47 263.88,65.71 v264.51,65.08 | v232.76,232.08 232.13,232.71 232.13,248.27 v233.08,249.23 | v212.44,248.91 212.44,221.92 210.22,219.7 210.22,207.31 209.9,207 209.9,202.55 v210.22,202.24 | v201.33,198.74 v204.51,201.92
  Bottom 0.254: v271.5,115.88 279.12,115.88 280.39,117.14 C07.K2 | v268.01,93.97 266.42,92.38 v264.51,92.38 | v264.51,65.08 262.29,62.85 260.07,62.85 256.26,59.04 247.05,59.04 246.42,58.41 244.19,58.41 237.84,52.06 212.76,52.06 206.41,45.71 196.89,45.71 195.93,44.75 D14.L1 | v232.76,232.08 235.94,232.08 A11.S1 | v233.08,249.23 232.76,248.91 226.1,248.91 224.19,247 221.97,247 221.33,246.37 219.43,246.37 216.89,248.91 v212.44,248.91 | v210.22,202.24 209.9,201.92 v204.51,201.92 | v201.33,198.74 199.74,197.15 195.93,197.15 B14.D1
MB_TO_DTB\
  Top 0.254: D12.F1 D12.J1 | D12.S1 223.56,29.2 223.24,29.51 223.24,33.64 222.6,34.28 222.6,42.53 223.56,43.49 223.56,46.98 D12.K1 223.56,48.25 223.56,53.33 D12.H1
  Bottom 0.254: D12.H1 223.24,54.28 221.02,56.5 D12.F1
MC00  (via drill 0.61)
  Top 0.254: v47.34,240.02 47.34,233.35 46.39,232.4 A26.S1 | v107.99,240.33 108.3,240.02 108.3,237.48 v109.89,235.89 | v171.17,230.49 171.8,229.86 171.8,222.87 v172.76,221.92 | v184.19,218.11 185.14,217.16 185.14,213.67 v186.09,212.71 | v221.02,59.36 219.43,57.77 219.43,55.87 v219.75,55.55 | v208.32,53.64 207.05,52.38 207.05,51.74 206.73,51.42 206.73,49.52 v207.05,49.2 | v202.28,47.93 200.38,46.03 200.38,43.49 201.97,41.9 v201.97,40.63 | v190.54,40.31 190.22,39.99 190.22,37.14 188.31,35.23 188.31,33.01 184.19,28.88 v184.19,28.56 | v163.87,26.98 161.96,26.98 v161.96,22.85 | v76.55,26.66 60.04,43.17 v60.04,183.18 | v61.95,188.27 63.22,189.54 63.22,196.84 64.49,198.11 64.49,198.74 63.85,199.38 63.85,210.81 v64.17,211.12 | v64.17,217.48 v64.17,221.29
  Route2 0.254: v230.54,62.22 234.03,62.22 234.99,63.17 239.11,63.17 D10.D2
  Route15 0.254: v172.76,221.92 v176.57,218.11 | v186.09,212.71 186.09,212.39 190.54,207.95 190.54,206.05 201.01,195.57 202.6,195.57 204.19,193.98 B13.E2 | v216.89,56.18 215.62,54.92 v214.98,55.55 | v50.52,223.51 50.52,225.41 47.98,227.95 47.98,229.54 46.39,231.13 A26.S1
  Bottom 0.254: B13.E2 205.46,193.34 210.54,193.34 B13.E1 | v47.34,240.02 83.22,240.02 83.54,240.33 86.4,240.33 86.71,240.02 107.67,240.02 v107.99,240.33 | v109.89,235.89 110.21,236.21 122.27,236.21 125.13,233.35 130.21,233.35 133.07,230.49 168.63,230.49 169.58,231.45 170.22,231.45 v171.17,230.49 | v176.57,218.11 v184.19,218.11 | v230.54,62.22 229.91,61.58 229.27,61.58 228.32,60.63 225.46,60.63 224.51,61.58 223.24,61.58 v221.02,59.36 | v219.75,55.55 219.11,56.18 v216.89,56.18 | v214.98,55.55 214.67,55.23 209.9,55.23 v208.32,53.64 | v207.05,49.2 206.73,48.88 204.19,48.88 203.24,47.93 v202.28,47.93 | v201.97,40.63 201.33,39.99 190.85,39.99 v190.54,40.31 | v184.19,28.56 183.87,28.25 181.01,28.25 179.42,26.66 170.53,26.66 170.22,26.98 167.99,26.98 167.68,26.66 164.18,26.66 v163.87,26.98 | v161.96,22.85 161.33,23.48 152.44,23.48 151.8,22.85 149.9,22.85 148.94,23.8 117.19,23.8 116.88,24.12 92.43,24.12 89.89,26.66 v76.55,26.66 | v60.04,183.18 60.04,188.27 v61.95,188.27 | v64.17,211.12 64.17,212.08 63.54,212.71 63.54,217.48 v64.17,217.48 | v64.17,221.29 63.85,220.97 58.46,220.97 56.87,222.55 56.87,222.87 56.23,223.51 v50.52,223.51
MC00\  (via drill 0.61)
  Top 0.254: v223.56,159.69 222.6,160.64 222.6,172.07 222.92,172.39 222.92,173.02 v221.97,173.98 | v201.97,174.93 200.38,176.52 v200.38,187.31 200.06,187.63 200.06,190.17 v199.74,190.49 | v243.88,254.94 244.83,253.99 244.83,236.52 245.78,235.57 A10.R1 | v200.06,255.58 199.74,255.26 199.74,223.51 199.11,222.87 v199.11,218.11 | v195.62,218.11 194.98,217.48 194.98,204.77 193.71,203.51 193.71,198.11 193.39,197.79 193.39,193.03 v192.44,192.08
  Bottom 0.254: v223.56,159.69 225.78,159.69 226.41,159.05 B11.T2 | v221.97,173.98 221.33,173.34 203.55,173.34 v201.97,174.93 | v200.38,187.31 201.65,188.58 202.92,188.58 204.51,190.17 207.36,190.17 B13.F1 | v243.88,254.94 243.56,255.26 200.38,255.26 v200.06,255.58 | v195.62,218.11 v199.11,218.11 | v192.44,192.08 192.76,191.76 196.25,191.76 197.52,190.49 v199.74,190.49
MC01  (via drill 0.61)
  Top 0.254: v44.49,219.06 44.49,222.55 44.17,222.87 44.17,227 43.22,227.95 A26.T1 | v89.25,220.97 90.84,222.55 v90.84,223.51 | v120.69,228.27 120.37,228.59 120.37,240.65 123.86,244.14 v123.86,247.96 | v184.19,253.99 184.5,253.67 184.5,250.18 185.14,249.54 186.73,249.54 186.73,249.86 187.04,250.18 187.04,259.7 186.41,260.34 186.41,262.24 187.36,263.19 v187.36,265.74 | v209.59,265.74 209.9,265.42 209.9,262.24 210.22,261.93 210.22,258.11 209.9,257.8 209.9,248.27 210.54,247.64 210.54,245.73 209.9,245.1 209.9,227.95 210.54,227.32 210.54,226.68 209.59,225.73 v209.59,223.19 | v200.38,218.43 200.06,218.11 200.06,204.46 199.74,204.14 199.74,195.25 204.51,190.49 204.51,187.95 B13.H2 205.14,186.68 207.36,184.46 B13.J1 208.32,183.5 209.27,182.55 209.27,160.96 209.59,160.64 v209.59,145.72 | v234.67,145.08 234.67,132.39 236.26,130.8 C11.E1 | v228.32,250.81 228.64,251.13 v228.64,253.67 | v223.56,252.4 223.24,252.72 223.24,255.89 222.6,256.53 222.6,258.75 v223.24,259.38 | v219.11,260.02 219.43,260.34 219.43,263.51 v217.21,265.74
  Route2 0.254: v203.87,221.92 v200.38,218.43
  Route15 0.254: v243.88,246.05 249.59,240.33 251.5,240.33 252.77,239.06 253.4,239.06 254.04,238.43 262.93,247.32 264.51,247.32 A08.L2
  Bottom 0.254: v44.49,219.06 87.35,219.06 v89.25,220.97 | v90.84,223.51 94.02,226.68 107.03,226.68 107.35,227 110.84,227 111.16,226.68 118.46,226.68 119.1,227.32 119.73,227.32 v120.69,228.27 | v123.86,247.96 125.13,249.23 136.56,249.23 136.88,249.54 141.96,249.54 145.45,253.04 149.9,253.04 150.21,252.72 160.37,252.72 163.55,255.89 175.3,255.89 175.93,256.53 178.15,256.53 179.42,255.26 183.23,255.26 184.19,254.3 v184.19,253.99 | v187.36,265.74 187.68,265.42 209.27,265.42 v209.59,265.74 209.9,265.42 216.89,265.42 v217.21,265.74 | v209.59,223.19 209.27,223.51 207.05,223.51 205.46,221.92 v203.87,221.92 | v234.67,145.08 234.03,145.72 v209.59,145.72 | v243.88,246.05 241.02,248.91 234.67,248.91 233.4,250.18 231.49,250.18 230.86,249.54 229.59,249.54 v228.32,250.81 | v228.64,253.67 227.37,252.4 v223.56,252.4 | v223.24,259.38 222.92,259.07 220.06,259.07 v219.11,260.02
MC01\  (via drill 0.61)
  Top 0.254: v202.92,172.71 202.92,182.55 201.97,183.5 B13.J2 | v235.94,172.71 236.26,172.39 236.26,168.9 B11.P1 | v209.59,64.12 209.27,64.44 209.27,79.68 209.59,80 209.59,90.47 207.68,92.38 207.68,93.65 206.09,95.24 206.09,111.75 206.73,112.38 206.73,129.21 207.36,129.84 207.36,132.07 206.73,132.7 v206.73,137.78 | v221.97,172.71 221.97,159.37 222.6,158.74 222.6,151.12 222.92,150.8 222.92,148.58 222.6,148.26 222.6,139.05 v222.92,138.74
  Bottom 0.254: v235.94,172.71 v221.97,172.71 v202.92,172.71 | v209.59,64.12 212.13,64.12 213.08,65.08 233.72,65.08 234.67,64.12 236.26,64.12 240.07,60.31 D10.E2 | v206.73,137.78 216.89,137.78 217.52,138.42 222.92,138.42 | 222.92,138.42 231.81,138.42 232.76,139.37 C11.B1 | 222.92,138.42 v222.92,138.74
MC02  (via drill 0.61)
  Top 0.254: D12.D2 214.67,62.85 214.67,60.95 v214.98,60.63 213.08,58.72 213.08,42.53 213.71,41.9 213.71,39.36 v212.76,38.4 | v212.13,220.33 213.71,218.74 213.71,205.41 212.44,204.14 212.44,178.74 | 212.44,178.74 v211.81,178.11 | v229.27,163.5 228.95,163.18 228.95,157.15 229.91,156.2 B11.U2 | v213.08,166.99 212.44,167.63 212.44,178.74 | v82.9,42.53 82.27,43.17 82.27,165.72 v80.68,167.31 | v71.79,170.17 70.2,171.76 70.2,200.65 v72.11,202.55 | v75.6,206.05 75.92,206.36 75.92,224.78 v75.6,225.09
  Bottom 0.254: v214.98,60.63 216.89,60.63 D12.E2 | 75.6,226.68 83.54,226.68 83.86,227 85.13,227 92.43,219.7 199.43,219.7 199.74,220.02 211.81,220.02 v212.13,220.33 | 75.6,226.68 47.66,226.68 46.71,225.73 A26.U1 | v211.81,178.11 208.63,178.11 B13.L1 | v229.27,163.5 229.27,166.36 213.71,166.36 v213.08,166.99 | v212.76,38.4 211.17,36.82 156.25,36.82 150.85,42.21 148.63,42.21 148.31,42.53 v82.9,42.53 | v80.68,167.31 77.82,170.17 v71.79,170.17 | v72.11,202.55 v75.6,206.05 | v75.6,225.09 75.6,226.68
MC02\  (via drill 0.61)
  Top 0.254: B13.M1 210.86,175.25 209.9,176.2 209.9,198.43 210.86,199.38 B13.C1 | v240.7,65.39 241.02,65.08 241.02,62.85 239.75,61.58 D10.F2 | v202.28,143.18 201.97,143.5 v201.97,150.17
  Route2 0.254: v198.47,159.69 195.62,162.55 201.01,167.95 201.01,168.26 201.65,168.9 202.6,168.9 v208.32,174.61
  Route15 0.254: v240.7,65.39 240.7,66.98 238.48,69.2 238.48,74.28 231.49,81.27 231.49,82.22 221.33,92.38 221.33,92.7 219.11,94.92 219.11,98.73 213.71,104.13 213.71,106.67 213.08,107.3 213.08,119.05 210.22,121.91 210.22,122.86 206.73,126.35 206.73,128.89 208.63,130.8 203.24,136.2 203.24,142.23 v202.28,143.18 | v201.97,150.17 200.38,151.75 200.38,157.79 v198.47,159.69
  Bottom 0.254: v208.32,174.61 B13.M1
MF00  (via drill 0.61)
  Top 0.254: v65.12,210.17 66.39,208.9 66.39,203.19 v65.12,201.92 | v67.35,193.34 67.03,193.03 67.03,173.98 67.66,173.34 67.66,172.71 v66.71,171.76 | v66.71,167.31 67.03,166.99 67.03,92.06 73.06,86.03 v73.06,32.69 | v153.71,32.69 156.25,32.69 156.25,33.64 160.69,38.09 v160.69,39.04 | v169.58,47.93 174.66,53.01 v174.66,53.64 | v176.57,54.28 178.15,55.87 178.15,60.95 v179.74,62.53 | v187.36,63.49 187.68,63.81 187.68,65.39 v192.44,70.16
  Route2 0.254: v169.58,47.93 v160.69,39.04 | v202.6,72.06 209.59,65.08 209.9,65.08 210.86,64.12 210.54,63.81 210.54,62.85 216.25,57.14 218.79,57.14 220.06,58.41 223.24,58.41 228,53.64 232.76,58.41 234.35,58.41 235.94,60 D11.E1
  Route15 0.254: v59.41,218.11 55.92,221.6 A25.V1 | v144.82,33.32 145.45,33.32 v146.72,32.06 | v192.44,70.16 193.39,70.16 v195.3,72.06
  Bottom 0.254: v59.41,218.11 59.41,210.17 v65.12,210.17 | v65.12,201.92 62.58,199.38 62.58,198.11 v67.35,193.34 | v66.71,167.31 v66.71,171.76 | v73.06,32.69 73.38,33.01 144.5,33.01 v144.82,33.32 | v146.72,32.06 147.04,32.37 149.58,32.37 150.21,33.01 153.39,33.01 v153.71,32.69 | v174.66,53.64 175.3,54.28 v176.57,54.28 | v179.74,62.53 180.06,62.22 186.09,62.22 v187.36,63.49 | v195.3,72.06 195.62,71.74 202.28,71.74 v202.6,72.06
MF00\  (via drill 0.61)
  Top 0.254: v238.8,58.72 238.48,59.04 238.48,77.77 237.84,78.41 237.84,89.52 241.02,92.7 241.02,123.18 v240.7,123.49 | v238.8,124.13 238.48,124.45 238.48,142.23 241.34,145.08 243.88,145.08 v243.88,150.17 | v307.38,149.53 307.38,154.61 307.69,154.93 v307.69,172.07 | v311.5,196.84 311.5,186.04 311.82,185.73 311.82,181.92 311.5,181.6 311.5,176.2 312.46,175.25 B05.M1
  Bottom 0.254: v238.8,58.72 238.48,58.41 234.99,58.41 234.03,57.46 D11.F1 | v240.7,123.49 240.07,124.13 v238.8,124.13 | v243.88,150.17 244.19,149.85 268.64,149.85 268.96,149.53 272.45,149.53 273.09,148.89 284.2,148.89 285.15,149.85 305.15,149.85 305.47,149.53 v307.38,149.53 | v307.69,172.07 309.28,173.66 311.5,173.66 312.14,174.3 B05.M1 | B04.D2 v311.5,196.84
MF01  (via drill 0.61)
  Top 0.254: v228,61.58 228,60.63 229.59,59.04 229.59,54.92 229.91,54.6 D11.H2 | v203.24,69.84 202.92,69.52 202.92,69.2 202.6,68.88 202.6,64.44 202.92,64.12 202.92,61.58 201.33,60 v201.33,59.04 | v192.44,57.14 190.85,55.55 190.85,49.52 v191.17,49.2 | v158.15,48.88 153.07,43.8 153.07,42.21 152.12,41.26 v152.12,36.18 | v67.98,33.96 57.5,44.44 57.5,73.97 57.82,74.28 57.82,91.11 56.87,92.06 56.87,145.72 54.33,148.26 54.33,202.55 49.57,207.31 v49.57,209.86 | v20.36,219.38 20.04,219.7 20.04,224.14 19.4,224.78 19.4,253.99 22.58,257.16 22.58,267.96 v26.71,272.09
  Route15 0.254: v218.16,69.52 v223.56,64.12
  Bottom 0.254: v228,61.58 227.37,62.22 225.46,62.22 v223.56,64.12 | v218.16,69.52 217.21,70.47 216.57,70.47 215.62,69.52 215.62,68.57 207.36,68.57 206.09,69.84 v203.24,69.84 | v201.33,59.04 200.7,58.41 193.71,58.41 v192.44,57.14 | v191.17,49.2 190.85,48.88 v158.15,48.88 | v152.12,36.18 133.07,36.18 130.53,33.64 68.3,33.64 v67.98,33.96 | v49.57,209.86 48.93,210.49 44.8,210.49 35.91,219.38 v20.36,219.38 | v26.71,272.09 32.1,277.48 44.49,277.48 45.44,276.53 A26.A1
MF01\  (via drill 0.61)
  Top 0.254: v226.41,103.81 225.78,103.18 225.78,88.25 226.1,87.94 226.1,76.19 225.78,75.87 225.78,52.38 226.73,51.42 D11.J2 | v266.42,123.81 266.42,134.61 266.1,134.93 266.1,138.74 266.74,139.37 266.74,147.31 267.37,147.94 267.37,154.61 267.05,154.93 v267.05,169.53 | v321.35,193.34 321.03,193.03 321.03,180.64 319.44,179.06 v319.44,176.2
  Bottom 0.254: v226.41,103.81 226.73,103.49 238.48,103.49 251.18,116.19 251.18,123.18 254.35,123.18 254.99,122.54 263.56,122.54 264.83,123.81 v266.42,123.81 | v267.05,169.53 288.01,169.53 288.64,170.17 308.01,170.17 308.96,171.12 B05.N1 310.23,171.76 311.5,173.02 314.36,173.02 317.22,175.88 319.12,175.88 v319.44,176.2 | v321.35,193.34 319.76,193.34 B04.E2
MF02  (via drill 0.61)
  Top 0.254: v216.89,50.79 v221.02,46.66 | v187.36,57.46 187.04,57.14 187.04,53.01 v184.82,50.79 | v178.79,44.75 169.58,35.55 v169.58,35.23 | v163.87,28.88 162.6,27.61 161.33,27.61 161.01,27.29 158.79,27.29 v158.79,27.93 | v149.58,21.89 148.63,20.94 130.53,20.94 v130.53,34.91 | v24.17,59.04 v20.67,62.53 | v1.94,222.55 2.89,223.51 2.89,233.35 v2.58,233.67 | v17.18,263.83 21.94,268.59 21.94,276.85 40.99,295.9 42.58,295.9 42.58,273.67 A26.B1
  Route2 0.254: v216.89,50.79 208.95,58.72 208.63,58.41 204.19,58.41 v202.6,60 | v184.82,50.79 v178.79,44.75 | v169.58,35.23 167.99,33.64 167.99,33.01 v163.87,28.88 | v155.61,27.93 v149.58,21.89
  Bottom 0.254: v221.02,46.66 221.33,46.34 231.18,46.34 232.76,44.75 D11.L1 | v202.6,60 200.06,60 199.11,59.04 188.95,59.04 v187.36,57.46 | v158.79,27.93 v155.61,27.93 | v130.53,34.91 129.26,36.18 53.06,36.18 30.2,59.04 v24.17,59.04 | v20.67,62.53 12.1,71.11 6.07,71.11 2.89,74.28 2.89,222.55 v1.94,222.55 | v2.58,233.67 2.58,258.43 11.47,258.43 16.86,263.83 v17.18,263.83
MF02\  (via drill 0.61)
  Top 0.254: v283.88,46.03 286.1,48.25 286.1,94.28 286.42,94.6 286.42,97.46 286.1,97.78 286.1,101.59 v287.37,102.86 | v296.58,103.18 298.17,104.76 298.17,156.52 v297.85,156.83 | v322.62,160.64 323.57,161.59 323.57,181.6 v323.25,181.92 | v320.71,195.89 320.39,195.57 320.39,182.55 319.44,181.6 B04.K2
  Bottom 0.254: v283.88,46.03 283.56,45.71 275.94,45.71 273.4,43.17 247.05,43.17 243.88,39.99 238.16,39.99 237.21,40.95 D11.M1 | v287.37,102.86 287.69,103.18 v296.58,103.18 | v297.85,156.83 301.66,156.83 302.3,156.2 305.15,156.2 306.11,157.15 309.92,157.15 312.77,160.01 321.66,160.01 322.3,160.64 v322.62,160.64 | v323.25,181.92 322.62,181.28 319.76,181.28 B04.K2 | v320.71,195.89 320.39,195.57 308.96,195.57 308.65,195.89 304.52,195.89 303.88,196.52 B05.D2
MK_BLK_END  (via drill 0.61)
  Top 0.254: v139.1,27.61 142.59,24.12 142.59,22.53 147.04,22.53 CD18.BU1 | v125.77,28.88 121,33.64 121,74.92 v122.91,76.82 | v243.88,196.84 v239.11,201.6 | v241.97,202.55 241.65,202.87 241.65,205.73 241.34,206.05 241.34,211.44 242.29,212.39 v242.29,217.16
  Route2 0.254: v144.5,85.08 144.5,86.03 148.31,89.84 148.31,90.79 152.12,94.6 152.12,98.41 175.61,121.91 180.38,121.91 192.12,133.65 192.44,133.65 193.08,134.29 193.08,134.93 197.84,139.69 197.84,140.32 205.78,148.26 206.41,148.26 218.16,160.01 218.48,160.01 223.87,165.4 225.46,165.4 229.59,169.53 230.54,169.53 231.49,170.49 231.49,172.39 250.23,191.12 250.23,192.71 250.54,193.03 250.54,194.3 248.96,195.89 v248.64,195.89 | v242.29,217.16 242.29,220.33 248.64,226.68 250.23,226.68 251.81,228.27 A09.T2
  Bottom 0.254: v139.1,27.61 138.78,27.29 127.35,27.29 v125.77,28.88 | v122.91,76.82 123.86,77.77 131.16,77.77 131.8,77.14 146.4,77.14 147.36,78.09 147.36,84.44 145.13,84.44 v144.5,85.08 | v248.64,195.89 248.32,195.57 245.15,195.57 v243.88,196.84 | v239.11,201.6 239.43,201.92 240.7,201.92 241.34,202.55 v241.97,202.55
MK_BLK_END\  (via drill 0.61)
  Top 0.254: v104.49,63.17 104.49,19.04 105.45,18.09 105.45,9.51 135.29,9.51 144.18,18.4 CD18.BV1 | v90.21,65.08 88.62,66.66 88.62,153.66 v88.3,153.98 | v118.46,168.58 117.83,169.21 117.83,173.34 v118.15,173.66 | v113.07,174.93 111.48,176.52 111.48,180.64 v113.07,182.23 | v115.61,184.46 117.19,186.04 117.19,194.3 116.88,194.61 116.88,197.15 121.64,201.92 v121.64,203.51 | v125.45,216.84 v125.45,207 | v162.28,238.11 162.28,248.27 162.91,248.91 165.14,248.91 v165.14,247.96 | v251.81,276.85 253.4,275.26 253.4,274.62 254.04,273.99 257.85,273.99 258.16,274.31 260.07,274.31 260.07,271.77 v259.75,271.45
  Route2 0.254: v121.64,203.51 121.96,203.51 v125.45,207 | v144.18,218.11 144.18,218.43 153.39,227.64 153.39,228.27 160.69,235.57 160.69,236.52 v162.28,238.11 | v198.79,252.72 200.38,252.72 202.6,250.49 213.71,261.61 217.52,261.61 218.16,262.24 224.51,262.24 231.81,269.55 231.81,270.18 233.4,271.77 234.03,271.77 237.84,275.58 237.84,276.53 239.11,277.8 248,277.8 248.32,278.12 250.54,278.12 v251.81,276.85
  Route15 0.254: v188,255.58 v183.55,251.13
  Bottom 0.254: v104.49,63.17 102.59,65.08 v90.21,65.08 | v88.3,153.98 85.13,157.15 85.13,159.69 85.44,159.69 92.75,166.99 116.88,166.99 v118.46,168.58 | v118.15,173.66 117.83,173.34 114.65,173.34 v113.07,174.93 | v113.07,182.23 115.29,184.46 v115.61,184.46 | v125.45,216.84 127.04,218.43 143.86,218.43 v144.18,218.11 | v165.14,247.96 166.41,246.68 168.95,246.68 169.26,246.37 173.07,246.37 176.25,249.54 181.96,249.54 v183.55,251.13 | v188,255.58 188,254.94 187.68,254.62 187.68,252.72 v198.79,252.72 | v259.75,271.45 261.02,270.18 261.34,270.18 A09.C1
MK_BLK_MK  (via drill 0.61)
  Top 0.254: v142.59,86.98 142.59,124.45 141.32,125.72 CD18.AE2 | v249.27,85.71 D10.A1 248.96,72.38 246.73,70.16 D10.B1
  Bottom 0.254: v142.59,86.98 226.73,86.98 228,85.71 228.64,85.71 228.95,86.03 248.96,86.03 v249.27,85.71
MK_BLK_START\  (via drill 0.61)
  Top 0.254: v119.42,129.84 117.83,128.26 117.83,125.4 v119.42,123.81 | v74.97,124.77 69.57,130.16 69.57,165.72 65.44,169.85 v65.12,169.85 | v74.65,173.02 75.28,173.66 v75.28,174.93 | v105.45,174.93 105.13,175.25 105.13,191.12 v106.72,192.71 | v127.04,196.52 127.35,196.84 127.35,201.6 128.94,203.19 128.94,204.77 129.89,205.73 129.89,208.9 v128.62,210.17 | v141.01,213.03 142.28,214.3 v142.28,222.55 | v159.74,235.89 159.1,236.52 159.1,240.33 v159.74,240.97 | v164.5,245.1 166.72,247.32 v166.72,247.64
  Route2 0.254: v121.96,132.39 v119.42,129.84 | v124.5,193.98 v127.04,196.52 | v166.72,247.64 171.49,252.4 171.8,252.4 183.87,264.47 184.82,264.47 185.14,264.78 204.19,264.78 207.36,267.96 211.49,267.96 225.14,281.61 229.91,281.61 237.84,289.55 239.43,289.55 240.07,290.18 245.15,290.18 258.8,276.53 261.34,276.53 A09.A1
  Route15 0.254: v119.42,123.81 v116.24,120.64 | v142.28,222.55 v154.34,234.62
  Bottom 0.254: v121.96,132.39 122.27,132.07 125.77,132.07 126.4,131.43 129.26,131.43 134.97,125.72 142.91,125.72 143.86,126.67 CD18.AF1 | v116.24,120.64 114.97,119.37 80.36,119.37 v74.97,124.77 | v65.12,169.85 65.12,173.34 65.76,173.34 66.39,173.98 70.2,173.98 71.16,173.02 v74.65,173.02 | v75.28,174.93 76.87,173.34 103.86,173.34 v105.45,174.93 | v106.72,192.71 107.03,192.39 122.91,192.39 v124.5,193.98 | v128.62,210.17 128.62,211.12 128.94,211.12 130.85,213.03 v141.01,213.03 | v154.34,234.62 155.29,235.57 155.93,235.57 156.56,236.21 159.42,236.21 v159.74,235.89 | v159.74,240.97 163.87,245.1 v164.5,245.1
MK_DATA\  (via drill 0.61)
  Top 0.254: v121.32,94.92 v123.86,92.38 | v75.6,103.49 75.92,103.81 v75.92,153.66 | v95.92,171.44 95.6,171.76 95.6,176.52 v95.92,176.83 | v175.93,206.68 176.25,207 v176.25,214.3
  Route2 0.254: v147.36,197.15 147.36,197.79 152.75,203.19 152.75,203.51 154.34,205.09 154.66,205.09 v156.25,206.68 | v176.25,214.3 180.06,218.11 181.33,218.11 207.05,243.83 207.68,243.83 208.32,243.19 209.9,244.78 209.9,245.1 223.24,258.43 223.56,258.43 224.19,259.07 224.19,260.02 236.57,272.4 238.16,272.4 239.11,271.45 239.43,271.77 250.54,271.77 252.45,269.86 v253.72,271.13
  Route15 0.254: v122.27,178.11 125.45,181.28 125.45,182.23 v137.83,194.61
  Bottom 0.254: v123.86,92.38 125.45,90.79 139.74,90.79 140.69,91.74 CD18.AU2 | v121.32,94.92 112.75,103.49 v75.6,103.49 | v75.92,153.66 75.92,157.15 81.63,157.15 v95.92,171.44 | v95.92,176.83 96.24,176.52 120.69,176.52 v122.27,178.11 | v137.83,194.61 138.78,195.57 145.13,195.57 146.72,197.15 v147.36,197.15 | v156.25,206.68 156.56,206.36 158.47,206.36 159.74,205.09 166.09,205.09 166.41,204.77 168.63,204.77 168.95,205.09 174.34,205.09 v175.93,206.68 | v253.72,271.13 255.62,273.04 A09.B1
MK_END  (via drill 0.61)
  Top 0.254: v125.77,135.56 126.08,135.88 126.08,136.83 127.35,138.1 127.35,148.26 v129.26,150.17 | v135.61,151.12 136.88,152.39 136.88,159.37 v138.47,160.96 | v141.32,163.5 141.01,163.82 141.01,166.68 140.05,167.63 140.05,168.9 v141.64,170.49 | v156.25,175.56 155.93,175.88 155.93,179.37 v157.52,180.96 | v170.22,200.65 163.87,207 163.87,216.21 168.63,220.97 168.63,224.14 v170.53,226.05 | v248.96,260.66 250.86,262.56 v250.86,265.74
  Route2 0.254: v125.77,135.56 v127.67,133.65 | v157.52,180.96 158.47,180.96 162.6,185.09 162.6,185.73 167.99,191.12 167.99,193.03 171.17,196.2 171.17,199.7 v170.22,200.65 | v170.53,226.05 170.53,226.68 190.54,246.68 v190.54,247 | v268.64,266.37 269.28,266.37 270.86,267.96 272.45,267.96 274.04,269.55 A08.C1
  Route15 0.254: v147.99,173.02 150.53,175.56 v150.85,175.56 | v217.21,247.32 223.56,253.67 226.1,251.13 226.41,251.13 227.68,249.86 229.27,249.86 229.59,249.54 230.86,249.54 241.02,259.7 242.29,259.7 242.92,259.07 247.37,259.07 v248.96,260.66
  Bottom 0.254: v127.67,133.65 127.99,133.65 134.66,126.99 CD18.AF2 | v129.26,150.17 130.21,151.12 v135.61,151.12 | v138.47,160.96 141.01,163.5 v141.32,163.5 | v141.64,170.49 144.18,173.02 v147.99,173.02 | v150.85,175.56 151.17,175.88 155.93,175.88 v156.25,175.56 | v190.54,247 191.17,246.37 216.25,246.37 v217.21,247.32 | v250.86,265.74 251.18,265.42 267.69,265.42 v268.64,266.37
MK_END\  (via drill 0.61)
  Top 0.254: v128.94,126.67 127.35,128.26 127.35,131.75 v127.99,132.39 | v137.83,142.23 138.78,143.18 138.78,146.99 139.42,147.62 139.42,153.98 138.47,154.93 v138.47,155.56 | v146.72,164.45 146.4,164.77 146.4,168.9 v147.99,170.49 | v154.02,171.76 155.29,173.02 155.29,181.92 154.02,183.18 v154.02,184.46 | v175.93,205.41 177.2,206.68 177.2,215.89 v176.88,216.21
  Route2 0.254: v127.99,132.39 v137.83,142.23 | v154.02,184.46 154.66,184.46 157.52,187.31 157.52,187.95 164.18,194.61 164.18,195.57 169.26,200.65 169.26,200.96 169.9,201.6 172.12,201.6 v175.93,205.41 | v184.19,216.21 184.82,216.21 223.87,255.26 232.45,255.26 245.15,267.96 251.5,267.96 v251.81,268.28
  Route15 0.254: v138.47,155.56 147.04,164.14 v146.72,164.45
  Bottom 0.254: v128.94,126.67 133.07,122.54 139.74,122.54 140.69,123.49 CD18.AH2 | v147.99,170.49 148.31,170.17 152.44,170.17 v154.02,171.76 | v176.88,216.21 v184.19,216.21 | v251.81,268.28 252.13,267.96 254.99,267.96 256.26,266.69 A09.D1
MKT  (via drill 0.61)
  Top 0.254: v200.7,116.51 200.38,116.83 200.38,122.54 201.01,123.18 201.01,125.72 200.38,126.35 200.38,150.8 | 200.38,150.8 201.33,151.75 B13.V2 | v207.36,162.55 206.73,163.18 206.73,165.72 v207.68,166.68 | v201.97,166.68 200.38,166.68 200.38,150.8 | v40.99,179.06 40.99,204.46 41.31,204.77 41.31,222.55 41.63,222.87 41.63,225.41 40.99,226.05 40.99,251.45 40.36,252.08 40.36,256.21 40.04,256.53 A26.H2 | v181.33,166.36 181.33,176.2 182.28,177.15 B15.L1
  Bottom 0.254: v200.7,116.51 199.74,115.56 181.96,115.56 181.01,114.61 176.88,114.61 C15.L2 | v207.36,162.55 208,163.18 211.81,163.18 212.76,162.23 216.89,162.23 B12.S2 | v207.68,166.68 207.36,166.36 202.28,166.36 v201.97,166.68 201.65,166.36 v181.33,166.36 | v40.99,179.06 124.81,179.06 125.13,179.37 127.04,179.37 127.35,179.06 160.37,179.06 162.91,176.52 181.01,176.52 181.96,177.47 B15.L1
